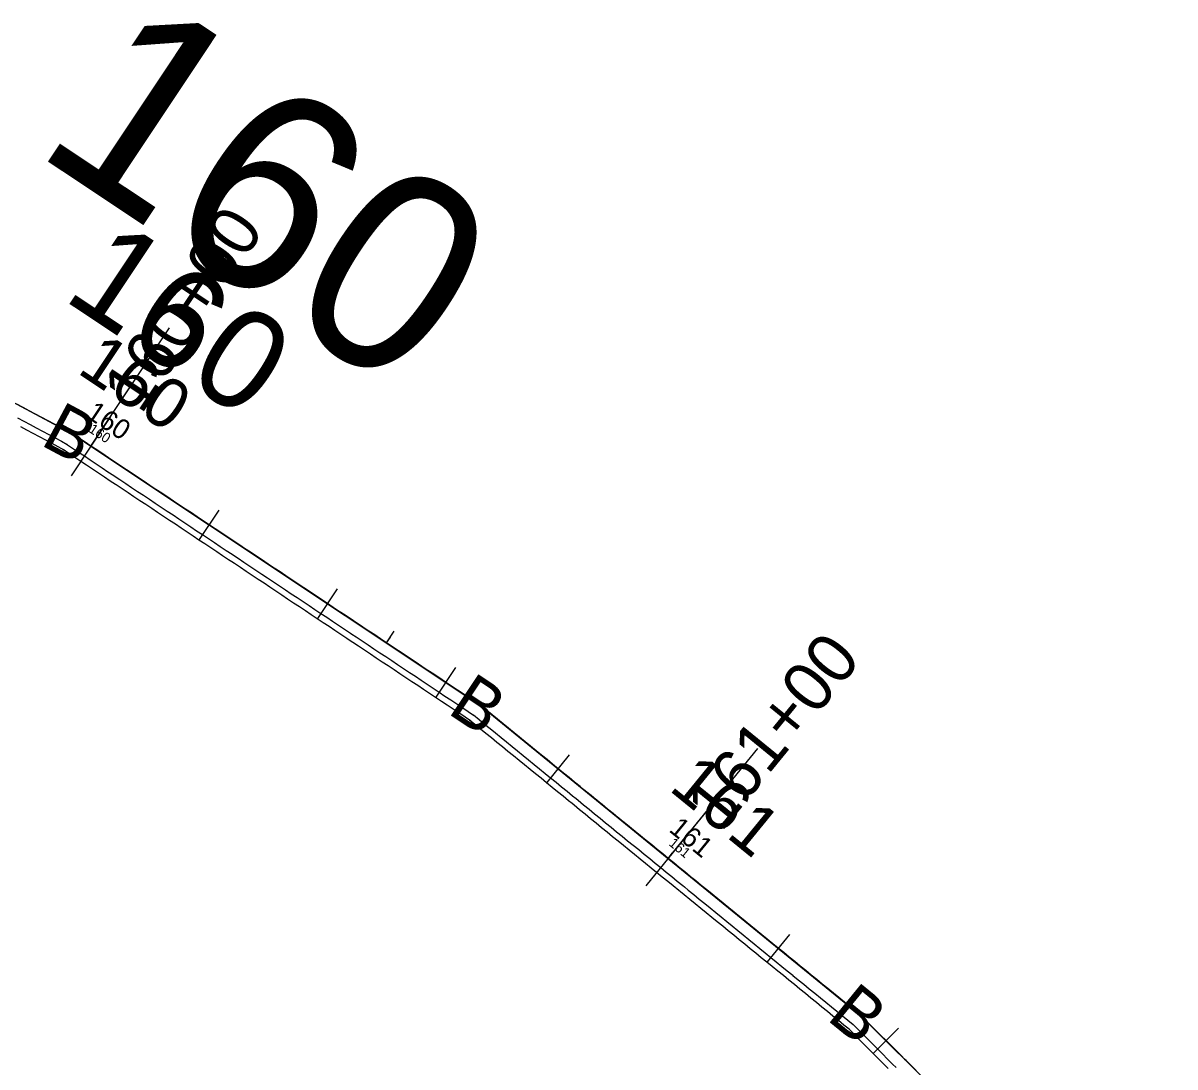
# Model space of a CAD drawing. Extents: x 1823824 to 1861612, y 706975 to 726130.
# Drawn here: x 1825933.2 to 1826095.4, y 715397.8 to 715544.8 of the extents above; entities that cross this region are included whole.
import ezdxf

# ---------------------------------------------------------------- set-up
doc = ezdxf.new("R2010")
doc.units = 0
for name, color, linetype in [('DR_X_Flood_Boundary', 7, 'Continuous'), ('GE_X_CL_10', 7, 'Continuous'), ('GE_X_CL_100', 7, 'Continuous'), ('GE_X_CL_20', 7, 'Continuous'), ('GE_X_CL_200', 7, 'Continuous'), ('GE_X_CL_50', 7, 'Continuous'), ('SC_Scratch3', 7, 'Continuous'), ('SC_Scratch5', 7, 'Continuous'), ('SC_Scratch6', 7, 'Continuous')]:
    doc.layers.add(name, color=color, linetype=linetype)

msp = doc.modelspace()

# ---------------------------------------------------------------- linework, layer by layer
at = {"layer": 'DR_X_Flood_Boundary'}
for p, q in [((1825901.75, 715507.52), (1825940.26, 715486.91)), ((1825940.26, 715486.91), (1825997.69, 715448.67)), ((1825997.69, 715448.67), (1826051.17, 715405.06)), ((1826051.17, 715405.06), (1826095.44, 715360.91))]:
    msp.add_line(p, q, dxfattribs=at)
at = {"layer": 'GE_X_CL_10'}
for p, q in [((1825942.8, 715485.22), (1825943.35, 715486.05)), ((1825984.41, 715457.51), (1825984.97, 715458.34)), ((1826024.08, 715427.15), (1826024.71, 715427.93))]:
    msp.add_line(p, q, dxfattribs=at)
at = {"layer": 'GE_X_CL_100'}
for p, q in [((1825942.8, 715485.22), (1825948.34, 715493.55)), ((1826024.08, 715427.15), (1826030.4, 715434.9))]:
    msp.add_line(p, q, dxfattribs=at)
at = {"layer": 'GE_X_CL_20'}
for p, q in [((1825942.8, 715485.22), (1825943.9, 715486.89)), ((1825984.41, 715457.51), (1825985.52, 715459.18)), ((1826024.08, 715427.15), (1826025.34, 715428.7))]:
    msp.add_line(p, q, dxfattribs=at)
at = {"layer": 'GE_X_CL_200'}
for p, q in [((1825942.8, 715485.22), (1825953.88, 715501.87)), ((1826024.08, 715427.15), (1826036.72, 715442.65))]:
    msp.add_line(p, q, dxfattribs=at)
at = {"layer": 'GE_X_CL_50'}
for p, q in [((1825942.8, 715485.22), (1825945.57, 715489.38)), ((1826024.08, 715427.15), (1826027.24, 715431.03))]:
    msp.add_line(p, q, dxfattribs=at)
at = {"layer": 'SC_Scratch3'}
for points in [[(1825932.37, 715491.15), (1825933.26, 715490.68), (1825934.14, 715490.21), (1825935.02, 715489.74), (1825935.9, 715489.26), (1825936.78, 715488.79), (1825937.66, 715488.32), (1825938.55, 715487.85), (1825939.43, 715487.38), (1825940.27, 715486.93), (1825940.31, 715486.9), (1825941.14, 715486.35), (1825941.97, 715485.79), (1825942.81, 715485.24), (1825943.64, 715484.68), (1825944.47, 715484.13), (1825945.3, 715483.57), (1825946.14, 715483.02), (1825946.97, 715482.47), (1825947.69, 715481.98), (1825947.8, 715481.91), (1825948.63, 715481.36), (1825949.46, 715480.8), (1825950.3, 715480.25), (1825951.13, 715479.7), (1825951.96, 715479.14), (1825952.79, 715478.59), (1825953.63, 715478.03), (1825954.46, 715477.48), (1825955.29, 715476.92), (1825956.12, 715476.37), (1825956.96, 715475.82), (1825957.79, 715475.26), (1825958.62, 715474.71), (1825959.45, 715474.15), (1825960.29, 715473.6), (1825961.12, 715473.05), (1825961.95, 715472.49), (1825962.78, 715471.94), (1825963.62, 715471.38), (1825964.08, 715471.07), (1825964.45, 715470.83), (1825965.28, 715470.27), (1825966.11, 715469.72), (1825966.95, 715469.17), (1825967.78, 715468.61), (1825968.61, 715468.06), (1825969.44, 715467.5), (1825970.27, 715466.95), (1825971.11, 715466.4), (1825971.94, 715465.84), (1825972.77, 715465.29), (1825973.6, 715464.73), (1825974.44, 715464.18), (1825975.27, 715463.62), (1825976.1, 715463.07), (1825976.93, 715462.52), (1825977.77, 715461.96), (1825978.6, 715461.41), (1825979.43, 715460.85), (1825980.26, 715460.3), (1825980.47, 715460.16), (1825981.1, 715459.75), (1825981.93, 715459.19), (1825982.76, 715458.64), (1825983.59, 715458.08), (1825984.43, 715457.53), (1825985.26, 715456.97), (1825986.09, 715456.42), (1825986.92, 715455.87), (1825987.76, 715455.31), (1825988.59, 715454.76), (1825989.42, 715454.2), (1825990.25, 715453.65), (1825991.08, 715453.09), (1825991.92, 715452.54), (1825992.75, 715451.99), (1825993.58, 715451.43), (1825994.41, 715450.88), (1825995.25, 715450.32)], [(1825976.1, 715463.06), (1825975.26, 715463.62), (1825974.43, 715464.17), (1825973.6, 715464.73), (1825972.77, 715465.28), (1825971.93, 715465.83), (1825971.1, 715466.39), (1825970.27, 715466.94), (1825969.44, 715467.5), (1825968.61, 715468.05), (1825967.77, 715468.6), (1825966.94, 715469.16), (1825966.11, 715469.71), (1825965.28, 715470.27), (1825964.44, 715470.82), (1825964.08, 715471.06), (1825963.61, 715471.38), (1825962.78, 715471.93), (1825961.95, 715472.48), (1825961.11, 715473.04), (1825960.28, 715473.59), (1825959.45, 715474.15), (1825958.62, 715474.7), (1825957.78, 715475.25), (1825956.95, 715475.81), (1825956.12, 715476.36), (1825955.29, 715476.92), (1825954.45, 715477.47), (1825953.62, 715478.03), (1825952.79, 715478.58), (1825951.96, 715479.13), (1825951.12, 715479.69), (1825950.29, 715480.24), (1825949.46, 715480.8), (1825948.63, 715481.35), (1825947.8, 715481.9), (1825947.69, 715481.98), (1825946.96, 715482.46), (1825946.13, 715483.01), (1825945.3, 715483.57), (1825944.47, 715484.12), (1825943.63, 715484.68), (1825942.8, 715485.23), (1825941.97, 715485.78), (1825941.14, 715486.34), (1825940.3, 715486.89), (1825940.26, 715486.92), (1825939.42, 715487.37), (1825938.54, 715487.84), (1825937.66, 715488.31), (1825936.78, 715488.78), (1825935.9, 715489.26), (1825935.01, 715489.73), (1825934.13, 715490.2), (1825933.25, 715490.67), (1825932.37, 715491.14)], [(1825932.46, 715489.2), (1825933.35, 715488.73), (1825934.23, 715488.26), (1825935.11, 715487.78), (1825935.99, 715487.31), (1825936.87, 715486.84), (1825937.75, 715486.37), (1825938.64, 715485.9), (1825939.48, 715485.45), (1825939.38, 715485.5), (1825940.21, 715484.95), (1825941.04, 715484.39), (1825941.88, 715483.84), (1825942.71, 715483.29), (1825943.54, 715482.73), (1825944.37, 715482.18), (1825945.2, 715481.62), (1825946.04, 715481.07), (1825946.76, 715480.59), (1825946.87, 715480.51), (1825947.7, 715479.96), (1825948.53, 715479.41), (1825949.37, 715478.85), (1825950.2, 715478.3), (1825951.03, 715477.74), (1825951.86, 715477.19), (1825952.7, 715476.64), (1825953.53, 715476.08), (1825954.36, 715475.53), (1825955.19, 715474.97), (1825956.03, 715474.42), (1825956.86, 715473.86), (1825957.69, 715473.31), (1825958.52, 715472.76), (1825959.36, 715472.2), (1825960.19, 715471.65), (1825961.02, 715471.09), (1825961.85, 715470.54), (1825962.69, 715469.99), (1825963.15, 715469.67), (1825963.52, 715469.43), (1825964.35, 715468.88), (1825965.18, 715468.32), (1825966.01, 715467.77), (1825966.85, 715467.21), (1825967.68, 715466.66), (1825968.51, 715466.11), (1825969.34, 715465.55), (1825970.18, 715465), (1825971.01, 715464.44), (1825971.84, 715463.89), (1825972.67, 715463.33), (1825973.51, 715462.78), (1825974.34, 715462.23), (1825975.17, 715461.67), (1825976, 715461.12), (1825976.84, 715460.56), (1825977.67, 715460.01), (1825978.5, 715459.46), (1825979.33, 715458.9), (1825979.54, 715458.76), (1825980.17, 715458.35), (1825981, 715457.79), (1825981.83, 715457.24), (1825982.66, 715456.68), (1825983.5, 715456.13), (1825984.33, 715455.58), (1825985.16, 715455.02), (1825985.99, 715454.47), (1825986.82, 715453.91), (1825987.66, 715453.36), (1825988.49, 715452.81), (1825989.32, 715452.25), (1825990.15, 715451.7), (1825990.99, 715451.14), (1825991.82, 715450.59), (1825992.65, 715450.03), (1825993.48, 715449.48), (1825994.32, 715448.93)], [(1825974.67, 715460.91), (1825973.83, 715461.47), (1825973, 715462.02), (1825972.17, 715462.58), (1825971.34, 715463.13), (1825970.5, 715463.69), (1825969.67, 715464.24), (1825968.84, 715464.79), (1825968.01, 715465.35), (1825967.18, 715465.9), (1825966.34, 715466.46), (1825965.51, 715467.01), (1825964.68, 715467.56), (1825963.85, 715468.12), (1825963.01, 715468.67), (1825962.65, 715468.92), (1825962.18, 715469.23), (1825961.35, 715469.78), (1825960.52, 715470.34), (1825959.68, 715470.89), (1825958.85, 715471.44), (1825958.02, 715472), (1825957.19, 715472.55), (1825956.35, 715473.11), (1825955.52, 715473.66), (1825954.69, 715474.21), (1825953.86, 715474.77), (1825953.02, 715475.32), (1825952.19, 715475.88), (1825951.36, 715476.43), (1825950.53, 715476.99), (1825949.7, 715477.54), (1825948.86, 715478.09), (1825948.03, 715478.65), (1825947.2, 715479.2), (1825946.37, 715479.76), (1825946.26, 715479.83), (1825945.53, 715480.31), (1825944.7, 715480.87), (1825943.87, 715481.42), (1825943.04, 715481.98), (1825942.2, 715482.53), (1825941.37, 715483.08), (1825940.54, 715483.64), (1825939.71, 715484.19), (1825938.88, 715484.75), (1825939.05, 715484.65), (1825938.21, 715485.1), (1825937.33, 715485.57), (1825936.44, 715486.04), (1825935.56, 715486.51), (1825934.68, 715486.98), (1825933.8, 715487.46), (1825932.92, 715487.93)], [(1826050.44, 715405.67), (1826049.66, 715406.31), (1826048.89, 715406.94), (1826048.11, 715407.57), (1826047.34, 715408.2), (1826046.56, 715408.83), (1826045.79, 715409.47), (1826045.01, 715410.1), (1826044.24, 715410.73), (1826043.46, 715411.36), (1826042.69, 715411.99), (1826042.69, 715411.99), (1826041.91, 715412.63), (1826041.14, 715413.26), (1826040.36, 715413.89), (1826039.59, 715414.52), (1826038.81, 715415.15), (1826038.04, 715415.79), (1826037.26, 715416.42), (1826036.49, 715417.05), (1826035.71, 715417.68), (1826034.94, 715418.31), (1826034.16, 715418.95), (1826033.39, 715419.58), (1826032.61, 715420.21), (1826031.84, 715420.84), (1826031.06, 715421.47), (1826030.29, 715422.11), (1826029.51, 715422.74), (1826028.74, 715423.37), (1826027.96, 715424), (1826027.43, 715424.43), (1826027.19, 715424.63), (1826026.41, 715425.27), (1826025.64, 715425.9), (1826024.86, 715426.53), (1826024.09, 715427.16), (1826023.31, 715427.79), (1826022.54, 715428.43), (1826021.76, 715429.06), (1826020.99, 715429.69), (1826020.21, 715430.32), (1826019.44, 715430.95), (1826018.66, 715431.59), (1826017.89, 715432.22), (1826017.11, 715432.85), (1826016.34, 715433.48), (1826015.56, 715434.11), (1826014.79, 715434.75), (1826014.01, 715435.38), (1826013.24, 715436.01), (1826012.46, 715436.64), (1826012.18, 715436.88), (1826011.69, 715437.27), (1826010.91, 715437.91), (1826010.14, 715438.54), (1826009.36, 715439.17), (1826008.59, 715439.8), (1826007.81, 715440.43), (1826007.04, 715441.07), (1826006.26, 715441.7), (1826005.49, 715442.33), (1826004.71, 715442.96), (1826003.94, 715443.59), (1826003.16, 715444.23), (1826002.39, 715444.86), (1826001.61, 715445.49), (1826000.84, 715446.12), (1826000.06, 715446.75), (1825999.29, 715447.39), (1825998.51, 715448.02), (1825997.74, 715448.65), (1825997.7, 715448.68), (1825996.91, 715449.21), (1825996.86, 715449.24), (1825996.07, 715449.76), (1825995.24, 715450.32), (1825994.41, 715450.87), (1825993.58, 715451.42), (1825992.74, 715451.98), (1825991.91, 715452.53), (1825991.08, 715453.09), (1825990.25, 715453.64), (1825989.42, 715454.2), (1825988.58, 715454.75), (1825987.75, 715455.3), (1825986.92, 715455.86), (1825986.09, 715456.41), (1825985.25, 715456.97), (1825984.42, 715457.52), (1825983.59, 715458.07), (1825982.76, 715458.63), (1825981.92, 715459.18), (1825981.09, 715459.74), (1825980.47, 715460.15), (1825980.26, 715460.29), (1825979.43, 715460.85), (1825978.59, 715461.4), (1825977.76, 715461.95), (1825976.93, 715462.51), (1825976.1, 715463.06)], [(1826048.83, 715403.7), (1826048.05, 715404.33), (1826047.28, 715404.97), (1826046.5, 715405.6), (1826045.73, 715406.23), (1826044.95, 715406.86), (1826044.18, 715407.49), (1826043.4, 715408.13), (1826042.63, 715408.76), (1826041.85, 715409.39), (1826041.08, 715410.01), (1826041.08, 715410.02), (1826040.3, 715410.65), (1826039.53, 715411.28), (1826038.75, 715411.92), (1826037.98, 715412.55), (1826037.2, 715413.18), (1826036.43, 715413.81), (1826035.65, 715414.44), (1826034.87, 715415.07), (1826034.1, 715415.71), (1826033.32, 715416.34), (1826032.55, 715416.97), (1826031.77, 715417.6), (1826031, 715418.23), (1826030.22, 715418.86), (1826029.44, 715419.49), (1826028.67, 715420.12), (1826027.89, 715420.75), (1826027.12, 715421.39), (1826026.34, 715422.02), (1826025.81, 715422.45), (1826025.57, 715422.65), (1826024.79, 715423.28), (1826024.02, 715423.91), (1826023.24, 715424.54), (1826022.46, 715425.17), (1826021.69, 715425.8), (1826020.91, 715426.43), (1826020.14, 715427.07), (1826019.36, 715427.7), (1826018.59, 715428.33), (1826017.81, 715428.96), (1826017.03, 715429.59), (1826016.26, 715430.22), (1826015.48, 715430.85), (1826014.71, 715431.49), (1826013.93, 715432.12), (1826013.16, 715432.75), (1826012.38, 715433.38), (1826011.61, 715434.01), (1826010.83, 715434.64), (1826010.55, 715434.88), (1826010.06, 715435.28), (1826009.28, 715435.91), (1826008.51, 715436.54), (1826007.73, 715437.17), (1826006.96, 715437.8), (1826006.18, 715438.44), (1826005.41, 715439.07), (1826004.63, 715439.7), (1826003.86, 715440.33), (1826003.08, 715440.96), (1826002.31, 715441.59), (1826001.53, 715442.23), (1826000.76, 715442.86), (1825999.98, 715443.49), (1825999.21, 715444.12), (1825998.43, 715444.75), (1825997.65, 715445.38), (1825996.88, 715446.02), (1825996.1, 715446.65), (1825996.27, 715446.53), (1825995.48, 715447.06), (1825995.43, 715447.09), (1825994.64, 715447.61), (1825993.81, 715448.17), (1825992.98, 715448.72), (1825992.15, 715449.28), (1825991.31, 715449.83), (1825990.48, 715450.38), (1825989.65, 715450.94), (1825988.82, 715451.49), (1825987.98, 715452.05), (1825987.15, 715452.6), (1825986.32, 715453.16), (1825985.49, 715453.71), (1825984.66, 715454.26), (1825983.82, 715454.82), (1825982.99, 715455.37), (1825982.16, 715455.93), (1825981.33, 715456.48), (1825980.49, 715457.04), (1825979.66, 715457.59), (1825979.04, 715458), (1825978.83, 715458.14), (1825978, 715458.7), (1825977.16, 715459.25), (1825976.33, 715459.81), (1825975.5, 715460.36), (1825974.67, 715460.91)], [(1825995.25, 715450.32), (1825996.08, 715449.77), (1825996.86, 715449.25), (1825996.91, 715449.22), (1825997.71, 715448.69), (1825997.74, 715448.66), (1825998.52, 715448.02), (1825999.29, 715447.39), (1826000.07, 715446.76), (1826000.84, 715446.13), (1826001.62, 715445.5), (1826002.39, 715444.86), (1826003.17, 715444.23), (1826003.94, 715443.6), (1826004.72, 715442.97), (1826005.49, 715442.34), (1826006.27, 715441.7), (1826007.04, 715441.07), (1826007.82, 715440.44), (1826008.59, 715439.81), (1826009.37, 715439.18), (1826010.14, 715438.54), (1826010.92, 715437.91), (1826011.69, 715437.28), (1826012.18, 715436.88), (1826012.47, 715436.65), (1826013.24, 715436.02), (1826014.02, 715435.39), (1826014.79, 715434.75), (1826015.57, 715434.12), (1826016.34, 715433.49), (1826017.12, 715432.86), (1826017.89, 715432.23), (1826018.67, 715431.59), (1826019.44, 715430.96), (1826020.22, 715430.33), (1826020.99, 715429.7), (1826021.77, 715429.07), (1826022.54, 715428.43), (1826023.32, 715427.8), (1826024.09, 715427.17), (1826024.87, 715426.54), (1826025.64, 715425.91), (1826026.42, 715425.27), (1826027.19, 715424.64), (1826027.44, 715424.44), (1826027.97, 715424.01), (1826028.74, 715423.38), (1826029.52, 715422.75), (1826030.29, 715422.11), (1826031.07, 715421.48), (1826031.84, 715420.85), (1826032.62, 715420.22), (1826033.39, 715419.59), (1826034.17, 715418.95), (1826034.94, 715418.32), (1826035.72, 715417.69), (1826036.49, 715417.06), (1826037.27, 715416.43), (1826038.04, 715415.79), (1826038.82, 715415.16), (1826039.59, 715414.53), (1826040.37, 715413.9), (1826041.14, 715413.27), (1826041.92, 715412.63), (1826042.69, 715412), (1826042.7, 715412), (1826043.47, 715411.37), (1826044.24, 715410.74), (1826045.02, 715410.11), (1826045.79, 715409.47), (1826046.57, 715408.84), (1826047.34, 715408.21), (1826048.12, 715407.58), (1826048.89, 715406.95), (1826049.67, 715406.31), (1826050.44, 715405.68), (1826051.18, 715405.08), (1826051.21, 715405.04), (1826051.92, 715404.34), (1826052.63, 715403.63), (1826053.34, 715402.93), (1826054.05, 715402.22), (1826054.76, 715401.51), (1826055.46, 715400.81), (1826056.17, 715400.1), (1826056.88, 715399.4), (1826057.37, 715398.9), (1826057.59, 715398.69), (1826058.3, 715397.98), (1826059, 715397.28)], [(1825994.32, 715448.93), (1825995.15, 715448.37), (1825995.93, 715447.85), (1825995.98, 715447.82), (1825996.77, 715447.29), (1825996.68, 715447.36), (1825997.46, 715446.72), (1825998.23, 715446.09), (1825999.01, 715445.46), (1825999.78, 715444.83), (1826000.56, 715444.2), (1826001.33, 715443.56), (1826002.11, 715442.93), (1826002.88, 715442.3), (1826003.66, 715441.67), (1826004.43, 715441.04), (1826005.21, 715440.4), (1826005.98, 715439.77), (1826006.76, 715439.14), (1826007.53, 715438.51), (1826008.31, 715437.88), (1826009.08, 715437.24), (1826009.86, 715436.61), (1826010.63, 715435.98), (1826011.12, 715435.58), (1826011.41, 715435.35), (1826012.18, 715434.72), (1826012.96, 715434.08), (1826013.73, 715433.45), (1826014.51, 715432.82), (1826015.28, 715432.19), (1826016.06, 715431.56), (1826016.83, 715430.92), (1826017.61, 715430.29), (1826018.38, 715429.66), (1826019.16, 715429.03), (1826019.93, 715428.4), (1826020.71, 715427.76), (1826021.48, 715427.13), (1826022.26, 715426.5), (1826023.03, 715425.87), (1826023.81, 715425.24), (1826024.58, 715424.6), (1826025.36, 715423.97), (1826026.13, 715423.34), (1826026.38, 715423.14), (1826026.91, 715422.71), (1826027.68, 715422.08), (1826028.46, 715421.44), (1826029.23, 715420.81), (1826030.01, 715420.18), (1826030.78, 715419.55), (1826031.56, 715418.92), (1826032.33, 715418.28), (1826033.11, 715417.65), (1826033.88, 715417.02), (1826034.66, 715416.39), (1826035.43, 715415.76), (1826036.21, 715415.12), (1826036.98, 715414.49), (1826037.76, 715413.86), (1826038.53, 715413.23), (1826039.31, 715412.6), (1826040.08, 715411.96), (1826040.86, 715411.33), (1826041.63, 715410.7), (1826041.64, 715410.69), (1826042.41, 715410.07), (1826043.18, 715409.44), (1826043.96, 715408.8), (1826044.73, 715408.17), (1826045.51, 715407.54), (1826046.28, 715406.91), (1826047.06, 715406.28), (1826047.83, 715405.64), (1826048.61, 715405.01), (1826049.38, 715404.38), (1826050.12, 715403.78), (1826050.03, 715403.86), (1826050.74, 715403.15), (1826051.45, 715402.44), (1826052.15, 715401.74), (1826052.86, 715401.03), (1826053.57, 715400.33), (1826054.28, 715399.62), (1826054.99, 715398.91), (1826055.69, 715398.21), (1826056.19, 715397.71)], [(1826059, 715397.27), (1826058.29, 715397.98), (1826057.58, 715398.68), (1826057.37, 715398.9), (1826056.87, 715399.39), (1826056.16, 715400.1), (1826055.46, 715400.8), (1826054.75, 715401.51), (1826054.04, 715402.21), (1826053.33, 715402.92), (1826052.62, 715403.63), (1826051.92, 715404.33), (1826051.21, 715405.04), (1826051.17, 715405.07), (1826050.44, 715405.67)], [(1826055.08, 715397.59), (1826054.37, 715398.29), (1826053.66, 715399), (1826052.95, 715399.71), (1826052.24, 715400.41), (1826051.54, 715401.12), (1826050.83, 715401.82), (1826050.12, 715402.53), (1826049.41, 715403.24), (1826049.57, 715403.1), (1826048.83, 715403.7)]]:
    msp.add_lwpolyline(points, dxfattribs=at)
at = {"layer": 'SC_Scratch5'}
for points in [[(1825945.57, 715489.38), (1825940.02, 715481.06)], [(1825960.83, 715476.22), (1825958.06, 715472.06)], [(1825977.48, 715465.14), (1825974.71, 715460.97)], [(1825994.12, 715454.05), (1825991.35, 715449.89)], [(1826010.16, 715441.73), (1826007, 715437.86)], [(1826027.24, 715431.03), (1826020.92, 715423.28)], [(1826041.16, 715416.45), (1826038, 715412.58)], [(1826056.51, 715403.27), (1826052.98, 715399.73)]]:
    msp.add_lwpolyline(points, dxfattribs=at)

# ---------------------------------------------------------------- texts
at = {"layer": 'GE_X_CL_10'}
for s, rotation, p in [('160', 326.3459, (1825942.37, 715487.3)), ('161', 320.8034, (1826024.07, 715429.1))]:
    msp.add_text(s, height=1.4, rotation=rotation, dxfattribs=at).set_placement(p)
at = {"layer": 'GE_X_CL_100'}
msp.add_text('160', height=14, rotation=326.3459, dxfattribs=at).set_placement((1825938.59, 715506.04))
at = {"layer": 'GE_X_CL_20'}
for s, rotation, p in [('160', 326.3459, (1825941.95, 715489.39)), ('161', 320.8034, (1826024.06, 715431.05))]:
    msp.add_text(s, height=2.8, rotation=rotation, dxfattribs=at).set_placement(p)
at = {"layer": 'GE_X_CL_200'}
msp.add_text('160', height=28, rotation=326.3459, dxfattribs=at).set_placement((1825934.38, 715526.87))
at = {"layer": 'GE_X_CL_50'}
for s, rotation, p in [('160', 326.3459, (1825940.69, 715495.63)), ('161', 320.8034, (1826024.02, 715436.88))]:
    msp.add_text(s, height=7, rotation=rotation, dxfattribs=at).set_placement(p)
at = {"layer": 'SC_Scratch5'}
for s, rotation, p in [('160+00', 56.3459, (1825949.87, 715489.53)), ('161+00', 50.8034, (1826031.53, 715430.75))]:
    msp.add_text(s, height=7, rotation=rotation, dxfattribs=at).set_placement(p)
at = {"layer": 'SC_Scratch6'}
for rotation, p in [(331.8453, (1825935.52, 715485.48)), (326.3459, (1825992.84, 715447.7)), (320.8034, (1826046.24, 715404.56))]:
    msp.add_text('B', height=7, rotation=rotation, dxfattribs=at).set_placement(p)

doc.saveas('drawing.dxf')
